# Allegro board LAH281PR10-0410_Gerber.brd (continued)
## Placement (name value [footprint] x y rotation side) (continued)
PC515  4.7U_0402_6.3V6M  [C_0402]  353.23 39.02 270 top
PC520  22U_0603_6.3V6M  [C_0603]  338.03 3.33 270 top
PC521  22U_0603_6.3V6M  [C_0603]  335.24 9.6 90 top
PC522  22U_0603_6.3V6M  [C_0603]  336.64 9.6 90 top
PC523  22U_0603_6.3V6M  [C_0603]  338.04 9.6 90 top
PC524  0.1U_0402_25V6  [C_0402]  314.91 7.58 270 top
PC525  22U_0603_6.3V6M  [C_0603]  336.63 3.36 270 top
PC526  1000P_0402_50V7K  [C_0402]  322.63 3.2 270 top
PC527  680P_0402_50V7K  [C_0402]  331.1 11.19 0 top
PC528  2200P_0402_50V7K  [C_0402]  315.8 7.58 270 top
PC529  22U_0603_6.3V6M  [C_0603]  335.23 3.33 270 top
PC530  10U_0805_25V6K  [C_0805]  317.32 8.1 270 top
PC531  0.1U_0603_25V7K  [C_0603]  324.56 10.75 270 top
PC532  10U_0805_25V6K  [C_0805]  319.1 7.98 270 top
PC533  4.7U_0402_6.3V6M  [C_0402]  324.86 3.31 270 top
PC700  0.1U_0402_25V6  [C_0402]  74.26 29.66 270 top
PC701  0.1U_0402_25V6  [C_0402]  74.21 27.12 0 top
PC702  0.01U_0402_25V6  [C_0402]  75.17 28.75 90 top
PC703  0.1U_0402_25V6  [C_0402]  102.32 6 180 top
PC704  10U_0805_25V6K  [C_0805]  102.32 9.92 180 top
PC705  10U_0805_25V6K  [C_0805]  102.33 8.21 180 top
PC706  2.2U_0402_10V6K  [C_0402]  73.94 21.63 270 top
PC707  1U_0603_25V6K  [C_0603]  74.3 25.47 0 top
PC708  0.047U_0603_25V7M~D  [C_0603]  74.31 24.27 0 top
PC709  2200P_0402_25V7K  [C_0402]  70.19 27.93 90 top
PC710  2200P_0402_50V7K  [C_0402]  102.34 6.9 180 top
PC711  100P_0402_50V8J  [C_0402]  67.73 28.83 270 top
PC712  100P_0402_50V8J  [C_0402]  65.55 26.2 0 top
PC713  10U_0805_25V6K  [C_0805]  71.88 8.01 90 bottom
PC714  10U_0805_25V6K  [C_0805]  73.61 8.01 90 bottom
PC715  10U_0805_25V6K  [C_0805]  71.87 8.01 90 top
PC716  10U_0805_25V6K  [C_0805]  73.61 8.01 90 top
PC717  680P_0402_50V7K  [C_0402]  96.92 2.76 0 top
PC718  0.1U_0402_25V6  [C_0402]  72.7 19.56 270 top
PC719  0.1U_0402_25V6  [C_0402]  71.95 17.79 180 top
PC720  0.1U_0402_25V6  [C_0402]  70.24 18.65 90 top
PC725  0.01U_0402_25V7K  [C_0402]  69.75 16.04 180 top
PC800  0.1U_0402_25V6  [C_0402]  103.9 34.06 270 top
PC801  2200P_0402_50V7K  [C_0402]  103.01 34.06 270 top
PC802  4.7U_0805_25V6K~D  [C_0805]  104.7 37.61 0 top
PC803  4.7U_0805_25V6K~D  [C_0805]  104.7 35.89 0 top
PC804  .1U_0603_25V7K  [C_0603]  106.44 33.13 90 top
PC805  4.7U_0402_6.3V6M  [C_0402]  107.58 33.53 90 top
PC806  330U_D2_2VM_R9M  [C_D2]  113.66 49.56 270 top
PC807  0.047U_0402_25V7K  [C_0402]  106.35 26.89 270 top
PC808  680P_0402_50V7K  [C_0402]  111.45 39.72 90 top
PC900  10U_0603_6.3V6M  [C_0603]  98.71 16.25 0 top
PC901  10U_0603_6.3V6M  [C_0603]  98.71 17.44 0 top
PC902  0.1U_0402_16V7K  [C_0402]  100.44 21.73 90 top
PC903  680P_0402_50V7K  [C_0402]  105.71 22.37 0 top
PC904  68P_0402_50V8J  [C_0402]  99.47 22.65 270 top
PC905  22U_0603_6.3V6M  [C_0603]  108.49 18.01 270 top
PC906  22U_0603_6.3V6M  [C_0603]  107.27 18.01 270 top
PC1100  1000P_0402_50V7K  [C_0402]  309.32 45.6 180 top
PC1101  10U_0402_6.3V6M  [C_0402]  312.29 38.12 270 top
PC1102  0.01UF_0402_25V7K  [C_0402]  308.42 43.83 270 top
PC1103  1000P_0402_50V7K  [C_0402]  309.9 50.89 90 top
PC1104  2200P_0402_50V7K  [C_0402]  309.32 43.83 270 top
PC1105  1000P_0402_50V7K  [C_0402]  308.61 49.48 270 top
PC1106  470P_0402_50V8J  [C_0402]  305.96 42.44 0 bottom
PC1107  0.015U_0402_25V7K  [C_0402]  308.92 47.39 270 top
PC1108  100P_0402_50V8J  [C_0402]  310.71 46.48 180 top
PC1109  1000P_0402_50V7K  [C_0402]  305.93 49.57 0 bottom
PC1110  2200P_0402_50V7K  [C_0402]  305.68 50.51 0 bottom
PC1111  1000P_0402_50V7K  [C_0402]  306.9 34.99 180 top
PC1112  2200P_0402_50V7K  [C_0402]  306.07 36.78 270 top
PC1113  15P_0402_50V8J  [C_0402]  305.08 47.72 90 top
PC1114  470P_0402_50V8J  [C_0402]  306.78 49.57 270 top
PC1115  2200P_0402_50V7K  [C_0402]  304.15 49.53 0 top
PC1116  470P_0402_50V8J  [C_0402]  305.13 34.29 180 top
PC1117  15P_0402_50V8J  [C_0402]  304.29 35.93 180 top
PC1118  470P_0402_50V8J  [C_0402]  304.12 45.37 90 bottom
PC1119  2200P_0402_50V7K  [C_0402]  303.34 34.16 90 top
PC1120  470P_0402_50V8J  [C_0402]  303.93 39.51 180 bottom
PC1121  56P_0402_50V8J  [C_0402]  302.4 47.75 180 top
PC1122  1000P_0402_50V7K  [C_0402]  301.49 48.66 0 top
PC1123  0.22U_0402_25V6K  [C_0402]  302.38 45.39 90 bottom
PC1124  100P_0402_50V8J  [C_0402]  300.55 34.17 180 top
PC1125  1000P_0402_50V7K  [C_0402]  300.55 35.05 180 top
PC1126  0.22U_0402_25V6K  [C_0402]  301.24 39.51 0 bottom
PC1127  0.1U_0402_25V6  [C_0402]  297.08 46.5 180 bottom
PC1128  0.01U_0402_50V7K  [C_0402]  296.16 47.51 0 top
PC1129  0.1U_0402_25V6  [C_0402]  297.84 40.4 180 top
PC1130  4.7U_0402_6.3V6M  [C_0402]  297.32 44.08 180 top
PC1131  0.1U_0402_25V6  [C_0402]  300.15 48.62 270 top
PC1132  0.1U_0402_25V6  [C_0402]  299.94 37.32 180 top
PC1133  0.1U_0402_25V6  [C_0402]  299.26 48.59 270 top
PC1135  0.1U_0402_25V6  [C_0402]  298.37 48.61 270 top
PC1136  0.1U_0402_25V6  [C_0402]  297.05 39 0 top
PC1137  3300P_0402_50V7K~D  [C_0402]  306.9 44.15 180 bottom
PC1140  2200P_0402_50V7K  [C_0402]  311.27 49.48 270 top
PC1204  100U_D3L_25VM_R60M  [C_T521D107M025ATE060]  296.26 17.34 0 top
PC1205  100U_D3L_25VM_R60M  [C_T521D107M025ATE060]  294.86 29.86 0 top
PC1206  2200P_0402_50V7K  [C_0402]  290.78 61.84 90 top
PC1207  0.1U_0402_25V7K  [C_0402]  290.78 61.84 90 bottom
PC1208  10U_0805_25VAK  [C_0805]  287.71 60.9 90 bottom
PC1209  10U_0805_25VAK  [C_0805]  289.46 60.9 90 bottom
PC1210  10U_0805_25VAK  [C_0805]  289.46 60.9 90 top
PC1211  10U_0805_25VAK  [C_0805]  287.71 60.9 90 top
PC1213  1U_0603_16V7K  [C_0603]  293.15 55.8 90 top
PC1214  0.22U_0603_25V7K  [C_0603]  293.19 59.58 180 top
PC1215  2.2U_0603_10V7K  [C_0603]  291.81 54.7 0 top
PC1216  1000P_0603_50V7K  [C_0603]  284.24 54.62 180 bottom
PC1217  2200P_0402_50V7K  [C_0402]  291.35 50.8 90 top
PC1218  0.1U_0402_25V7K  [C_0402]  291.35 50.8 90 bottom
PC1219  10U_0805_25VAK  [C_0805]  290.01 49.84 90 top
PC1220  10U_0805_25VAK  [C_0805]  290.01 49.84 90 bottom
PC1221  10U_0805_25VAK  [C_0805]  287.98 49.84 90 bottom
PC1222  10U_0805_25VAK  [C_0805]  287.98 49.84 90 top
PC1223  1U_0603_16V7K  [C_0603]  293.47 44.77 90 top
PC1224  0.22U_0603_25V7K  [C_0603]  293.42 48.55 180 top
PC1225  2.2U_0603_10V7K  [C_0603]  291.99 43.65 0 top
PC1226  1000P_0603_50V7K  [C_0603]  284.11 43.83 0 bottom
PC1227  2200P_0402_50V7K  [C_0402]  291.54 41.31 90 bottom
PC1228  0.1U_0402_25V7K  [C_0402]  291.54 41.31 90 top
PC1229  10U_0805_25VAK  [C_0805]  290.22 40.39 90 bottom
PC1230  10U_0805_25VAK  [C_0805]  288.47 40.41 90 bottom
PC1231  10U_0805_25VAK  [C_0805]  290.22 40.39 90 top
PC1232  10U_0805_25VAK  [C_0805]  288.47 40.41 90 top
PC1233  0.22U_0603_25V7K  [C_0603]  293.29 38.83 180 top
PC1234  1U_0603_16V7K  [C_0603]  293.21 35.05 90 top
PC1235  2.2U_0603_10V7K  [C_0603]  291.89 33.92 0 top
PC1236  1000P_0603_50V7K  [C_0603]  283.86 34.94 0 bottom
PC1237  2200P_0402_50V7K  [C_0402]  288.54 32.49 180 bottom
PC1238  0.1U_0402_25V7K  [C_0402]  288.54 32.49 180 top
PC1239  10U_0805_25VAK  [C_0805]  288.83 29.35 180 top
PC1240  10U_0805_25VAK  [C_0805]  288.83 29.35 180 bottom
PC1241  10U_0805_25VAK  [C_0805]  288.83 31.13 180 bottom
PC1242  10U_0805_25VAK  [C_0805]  288.83 31.13 180 top
PC1243  0.22U_0603_25V7K  [C_0603]  293.17 27.58 180 top
PC1244  1U_0603_16V7K  [C_0603]  293.13 23.88 90 top
PC1245  2.2U_0603_10V7K  [C_0603]  291.79 22.79 0 top
PC1246  1000P_0603_50V7K  [C_0603]  284.17 23.19 90 bottom
PC1300  330U_D2_2.5V_R6M  [C_D2]  272.67 42.1 0 bottom
PC1301  330U_D2_2.5V_R6M  [C_D2]  272.46 56.89 0 bottom
PC1302  22U_0603_6.3VAM  [C_0603]  269.69 45.3 270 top
PC1303  22U_0603_6.3VAM  [C_0603]  250.59 53.04 90 bottom
PC1304  22U_0603_6.3VAM  [C_0603]  249.4 57.26 270 bottom
PC1305  22U_0603_6.3VAM  [C_0603]  241.4 53.08 90 bottom
PC1306  22U_0603_6.3VAM  [C_0603]  269.73 54.18 270 bottom
PC1307  22U_0603_6.3VAM  [C_0603]  249.34 53.03 90 bottom
PC1308  22U_0603_6.3VAM  [C_0603]  269.69 49.74 270 top
PC1309  22U_0603_6.3VAM  [C_0603]  268.47 49.75 270 bottom
PC1310  22U_0603_6.3VAM  [C_0603]  269.69 49.75 270 bottom
PC1311  22U_0603_6.3VAM  [C_0603]  268.48 58.09 270 top
PC1312  22U_0603_6.3VAM  [C_0603]  268.48 49.76 270 top
PC1313  22U_0603_6.3VAM  [C_0603]  268.5 54.18 270 bottom
PC1314  22U_0603_6.3VAM  [C_0603]  269.75 58.09 270 top
PC1315  22U_0603_6.3VAM  [C_0603]  269.69 45.3 270 bottom
PC1316  22U_0603_6.3VAM  [C_0603]  269.72 54.18 270 top
PC1317  22U_0603_6.3VAM  [C_0603]  242.7 53.05 90 bottom
PC1318  22U_0603_6.3VAM  [C_0603]  243.95 53.05 90 bottom
PC1319  22U_0603_6.3VAM  [C_0603]  250.61 57.28 270 bottom
PC1320  22U_0603_6.3VAM  [C_0603]  269.74 58.09 270 bottom
PC1321  22U_0603_6.3VAM  [C_0603]  268.47 58.08 270 bottom
PC1322  22U_0603_6.3VAM  [C_0603]  248.06 53.05 90 bottom
PC1323  22U_0603_6.3VAM  [C_0603]  268.5 54.18 270 top
PC1324  10U_0402_6.3VAM  [C_0402]  248.8 52.02 270 bottom
PC1325  10U_0402_6.3VAM  [C_0402]  245.87 48.93 90 bottom
PC1326  10U_0402_6.3VAM  [C_0402]  242.2 48.98 90 bottom
PC1327  10U_0402_6.3VAM  [C_0402]  246.96 53.57 90 bottom
PC1328  10U_0402_6.3VAM  [C_0402]  246.96 52.02 270 bottom
PC1329  10U_0402_6.3VAM  [C_0402]  247.91 52.02 270 bottom
PC1330  10U_0402_6.3VAM  [C_0402]  245.99 52.02 270 bottom
PC1331  10U_0402_6.3VAM  [C_0402]  241.25 48.98 90 bottom
PC1332  10U_0402_6.3VAM  [C_0402]  249.69 52.02 270 bottom
PC1333  10U_0402_6.3VAM  [C_0402]  244.93 48.93 90 bottom
PC1334  10U_0402_6.3VAM  [C_0402]  244.13 52.02 270 bottom
PC1335  10U_0402_6.3VAM  [C_0402]  243.11 48.97 90 bottom
PC1336  10U_0402_6.3VAM  [C_0402]  245.04 53.6 90 bottom
PC1337  10U_0402_6.3VAM  [C_0402]  245.05 52.02 270 bottom
PC1338  10U_0402_6.3VAM  [C_0402]  244.01 48.95 90 bottom
PC1339  10U_0402_6.3VAM  [C_0402]  242.3 52.01 270 bottom
PC1340  10U_0402_6.3VAM  [C_0402]  245.99 53.58 90 bottom
PC1341  10U_0402_6.3VAM  [C_0402]  250.65 52.02 270 bottom
PC1342  10U_0402_6.3VAM  [C_0402]  246.81 48.91 90 bottom
PC1343  10U_0402_6.3VAM  [C_0402]  243.22 52.02 270 bottom
PC1344  10U_0402_6.3VAM  [C_0402]  241.35 52.04 270 bottom
PC1345  1U_0201_6.3VAM  [C_0201]  245.14 47.75 270 bottom
PC1346  1U_0201_6.3VAM  [C_0201]  245.72 47.73 270 bottom
PC1347  1U_0201_6.3VAM  [C_0201]  246.31 47.73 270 bottom
PC1348  1U_0201_6.3VAM  [C_0201]  242.21 47.77 270 bottom
PC1349  1U_0201_6.3VAM  [C_0201]  241.62 47.76 270 bottom
PC1350  1U_0201_6.3VAM  [C_0201]  241.66 45.47 90 bottom
PC1351  1U_0201_6.3VAM  [C_0201]  241.05 45.48 90 bottom
PC1352  1U_0201_6.3VAM  [C_0201]  242.24 45.48 90 bottom
PC1353  1U_0201_6.3VAM  [C_0201]  248.77 48.15 270 bottom
PC1354  1U_0201_6.3VAM  [C_0201]  248.2 48.16 270 bottom
PC1355  1U_0201_6.3VAM  [C_0201]  247.61 48.15 270 bottom
PC1356  1U_0201_6.3VAM  [C_0201]  244.04 45.49 90 bottom
PC1357  1U_0201_6.3VAM  [C_0201]  243.43 45.5 90 bottom
PC1358  1U_0201_6.3VAM  [C_0201]  242.83 45.49 90 bottom
PC1359  1U_0201_6.3VAM  [C_0201]  245.85 45.48 90 bottom
PC1360  1U_0201_6.3VAM  [C_0201]  245.26 45.47 90 bottom
PC1361  1U_0201_6.3VAM  [C_0201]  244.65 45.48 90 bottom
PC1362  1U_0201_6.3VAM  [C_0201]  251.89 49.74 270 bottom
PC1363  1U_0201_6.3VAM  [C_0201]  252.46 49.74 270 bottom
PC1364  1U_0201_6.3VAM  [C_0201]  251.98 50.68 90 bottom
PC1365  1U_0201_6.3VAM  [C_0201]  244.54 47.75 270 bottom
PC1366  1U_0201_6.3VAM  [C_0201]  243.94 47.75 270 bottom
PC1367  1U_0201_6.3VAM  [C_0201]  249.35 48.16 270 bottom
PC1368  1U_0201_6.3VAM  [C_0201]  251.99 56.82 270 bottom
PC1369  1U_0201_6.3VAM  [C_0201]  243.36 47.75 270 bottom
PC1370  1U_0201_6.3VAM  [C_0201]  242.78 47.75 270 bottom
PC1371  1U_0201_6.3VAM  [C_0201]  252.57 54.91 270 bottom
PC1372  1U_0201_6.3VAM  [C_0201]  250.54 48.16 270 bottom
PC1373  1U_0201_6.3VAM  [C_0201]  249.9 49.37 90 bottom
PC1374  1U_0201_6.3VAM  [C_0201]  248.14 49.35 90 bottom
PC1375  1U_0201_6.3VAM  [C_0201]  247.55 49.36 90 bottom
PC1376  1U_0201_6.3VAM  [C_0201]  241.05 47.76 270 bottom
PC1377  1U_0201_6.3VAM  [C_0201]  252.55 50.68 90 bottom
PC1378  1U_0201_6.3VAM  [C_0201]  250.15 45.8 90 bottom
PC1379  1U_0201_6.3VAM  [C_0201]  250.73 45.81 90 bottom
PC1380  1U_0201_6.3VAM  [C_0201]  248.72 49.35 90 bottom
PC1381  1U_0201_6.3VAM  [C_0201]  250.49 49.34 90 bottom
PC1382  1U_0201_6.3VAM  [C_0201]  249.31 49.36 90 bottom
PC1383  1U_0201_6.3VAM  [C_0201]  246.9 47.76 270 bottom
PC1384  1U_0201_6.3VAM  [C_0201]  249.94 48.15 270 bottom
PC1385  1U_0201_6.3VAM  [C_0201]  248.3 45.81 90 bottom
PC1386  1U_0201_6.3VAM  [C_0201]  248.93 45.81 90 bottom
PC1387  1U_0201_6.3VAM  [C_0201]  249.57 45.81 90 bottom
PC1388  1U_0201_6.3VAM  [C_0201]  246.45 45.48 90 bottom
PC1389  1U_0201_6.3VAM  [C_0201]  247.04 45.48 90 bottom
PC1390  1U_0201_6.3VAM  [C_0201]  247.69 45.8 90 bottom
PC1391  1U_0201_6.3VAM  [C_0201]  252.55 56.82 270 bottom
PC1392  1U_0201_6.3VAM  [C_0201]  252.01 54.91 270 bottom
PC1393  330U_D2_2.5V_R6M  [C_D2]  272.76 47.25 0 bottom
PC1394  330U_D2_2.5V_R6M  [C_D2]  242.85 42.57 0 bottom
PC1395  22U_0603_6.3VAM  [C_0603]  267.23 58.1 270 bottom
PC1396  22U_0603_6.3VAM  [C_0603]  267.23 58.1 270 top
PC1397  22U_0603_6.3VAM  [C_0603]  268.46 45.3 270 bottom
PC1398  22U_0603_6.3VAM  [C_0603]  268.46 45.3 270 top
PC1399  22U_0603_6.3VAM  [C_0603]  267.26 54.18 270 top
PC1400  22U_0603_6.3VAM  [C_0603]  267.26 54.18 270 bottom
PC1401  10U_0402_6.3VAM  [C_0402]  241.95 57.74 90 bottom
PC1402  10U_0402_6.3VAM  [C_0402]  240.14 56.66 270 bottom
PC1403  10U_0402_6.3VAM  [C_0402]  241.06 56.72 270 bottom
PC1404  10U_0402_6.3VAM  [C_0402]  242.91 56.71 270 bottom
PC1405  10U_0402_6.3VAM  [C_0402]  241.98 56.68 270 bottom
PC1406  10U_0402_6.3VAM  [C_0402]  243.81 56.7 270 bottom
PC1407  10U_0402_6.3VAM  [C_0402]  245.67 56.7 270 bottom
PC1408  10U_0402_6.3VAM  [C_0402]  246.58 56.7 270 bottom
PC1409  10U_0402_6.3VAM  [C_0402]  248.36 56.68 270 bottom
PC1410  10U_0402_6.3VAM  [C_0402]  245.67 57.75 90 bottom
PC1411  10U_0402_6.3VAM  [C_0402]  246.58 57.75 90 bottom
PC1412  10U_0402_6.3VAM  [C_0402]  248.36 57.74 90 bottom
PC1413  10U_0402_6.3VAM  [C_0402]  247.47 57.75 90 bottom
PC1414  10U_0402_6.3VAM  [C_0402]  240.99 57.72 90 bottom
PC1415  10U_0402_6.3VAM  [C_0402]  242.86 57.75 90 bottom
PC1416  10U_0402_6.3VAM  [C_0402]  250.51 58.24 0 bottom
PC1417  10U_0402_6.3VAM  [C_0402]  252.17 52.64 90 bottom
PC1418  10U_0402_6.3VAM  [C_0402]  247.47 56.68 270 bottom
PC1419  10U_0402_6.3VAM  [C_0402]  244.74 56.68 270 bottom
PC1420  10U_0402_6.3VAM  [C_0402]  244.74 57.75 90 bottom
PC1421  10U_0402_6.3VAM  [C_0402]  243.81 57.75 90 bottom
PC1500  470U_X_2VM_R6M  [C_X]  275.84 14.62 180 bottom
PC1502  22U_0603_6.3VAM  [C_0603]  267 29.4 45 top
PC1503  22U_0603_6.3VAM  [C_0603]  267.01 29.39 45 bottom
PC1504  22U_0603_6.3VAM  [C_0603]  266.13 30.26 45 bottom
PC1505  22U_0603_6.3VAM  [C_0603]  246.52 39.51 0 bottom
PC1506  22U_0603_6.3VAM  [C_0603]  267.85 28.53 45 top
PC1507  22U_0603_6.3VAM  [C_0603]  269.62 26.68 45 bottom
PC1508  22U_0603_6.3VAM  [C_0603]  268.69 27.63 45 top
PC1509  22U_0603_6.3VAM  [C_0603]  268.7 27.63 45 bottom
PC1510  22U_0603_6.3VAM  [C_0603]  269.61 26.67 45 top
PC1511  22U_0603_6.3VAM  [C_0603]  267.85 28.52 45 bottom
PC1512  22U_0603_6.3VAM  [C_0603]  250.33 39.51 180 bottom
PC1513  22U_0603_6.3VAM  [C_0603]  241.31 39.51 0 bottom
PC1514  22U_0603_6.3VAM  [C_0603]  245.48 39.61 180 bottom
PC1515  10U_0402_6.3VAM  [C_0402]  249.19 36.74 90 bottom
PC1516  10U_0402_6.3VAM  [C_0402]  247.39 36.75 90 bottom
PC1517  10U_0402_6.3VAM  [C_0402]  244.69 36.79 90 bottom
PC1518  10U_0402_6.3VAM  [C_0402]  248.3 36.74 90 bottom
PC1519  10U_0402_6.3VAM  [C_0402]  241.9 36.78 90 bottom
PC1520  10U_0402_6.3VAM  [C_0402]  245.62 36.75 90 bottom
PC1521  10U_0402_6.3VAM  [C_0402]  242.82 36.79 90 bottom
PC1522  10U_0402_6.3VAM  [C_0402]  246.5 36.75 90 bottom
PC1523  10U_0402_6.3VAM  [C_0402]  240.97 36.77 90 bottom
PC1524  10U_0402_6.3VAM  [C_0402]  243.77 36.81 90 bottom
PC1525  1U_0201_6.3VAM  [C_0201]  250.58 38.53 270 bottom
PC1526  1U_0201_6.3VAM  [C_0201]  251.16 38.54 270 bottom
PC1527  1U_0201_6.3VAM  [C_0201]  249.97 36.62 90 bottom
PC1528  1U_0201_6.3VAM  [C_0201]  250.56 36.62 90 bottom
PC1529  1U_0201_6.3VAM  [C_0201]  251.15 36.63 90 bottom
PC1530  1U_0201_6.3VAM  [C_0201]  252.14 40.36 90 bottom
PC1531  1U_0201_6.3VAM  [C_0201]  252.73 40.35 90 bottom
PC1532  1U_0201_6.3VAM  [C_0201]  252.84 37.39 90 bottom
PC1533  1U_0201_6.3VAM  [C_0201]  252.81 39.2 270 bottom
PC1534  1U_0201_6.3VAM  [C_0201]  252.26 37.39 90 bottom
PC1535  1U_0201_6.3VAM  [C_0201]  250 38.54 270 bottom
PC1536  1U_0201_6.3VAM  [C_0201]  252.23 39.2 270 bottom
PC1600  22U_0603_6.3VAM  [C_0603]  273.61 61.11 270 top
PC1601  22U_0603_6.3VAM  [C_0603]  272.39 61.11 270 top
PC1602  22U_0603_6.3VAM  [C_0603]  271.14 61.11 270 top
PC1603  22U_0603_6.3VAM  [C_0603]  269.9 61.11 270 top
PC1604  22U_0603_6.3VAM  [C_0603]  268.71 61.11 270 top
PC1605  22U_0603_6.3VAM  [C_0603]  268.71 61.11 270 bottom
PC1606  22U_0603_6.3VAM  [C_0603]  269.9 61.11 270 bottom
PC1607  22U_0603_6.3VAM  [C_0603]  271.14 61.11 270 bottom
PC1608  22U_0603_6.3VAM  [C_0603]  272.39 61.11 270 bottom
PC1609  22U_0603_6.3VAM  [C_0603]  273.61 61.11 270 bottom
PC1610  10U_0402_6.3VAM  [C_0402]  274.71 61.11 270 bottom
PC1611  10U_0402_6.3VAM  [C_0402]  267.58 60.8 270 top
PC1612  10U_0402_6.3VAM  [C_0402]  266.67 60.8 270 top
PC1613  10U_0402_6.3VAM  [C_0402]  265.76 60.8 270 top
PC1614  10U_0402_6.3VAM  [C_0402]  267.58 60.8 270 bottom
PC1615  10U_0402_6.3VAM  [C_0402]  266.67 60.8 270 bottom
PC1616  10U_0402_6.3VAM  [C_0402]  265.76 60.8 270 bottom
PC1617  1U_0201_6.3VAM  [C_0201]  274.58 60.95 270 top
PC1700  2200P_0402_50V7K  [C_0402]  293.32 19.76 90 top
PC1701  0.1U_0402_25V7K  [C_0402]  293.32 19.76 90 bottom
PC1702  10U_0603_25V6M  [C_0603]  291.02 19.7 90 bottom
PC1703  10U_0603_25V6M  [C_0603]  292.25 19.66 90 bottom
PC1704  10U_0603_25V6M  [C_0603]  291.02 19.7 90 top
PC1705  10U_0603_25V6M  [C_0603]  292.25 19.66 90 top
PC1706  0.22U_0603_25V7K  [C_0603]  293.38 17.67 180 top
PC1707  1U_0603_16V7K  [C_0603]  293.29 13.92 90 top
PC1708  2.2U_0603_10V7K  [C_0603]  291.98 12.71 0 top
PC1709  1000P_0603_50V7K  [C_0603]  285 13.27 90 bottom
PC1710  10U_0603_25V6M  [C_0603]  289.82 19.69 90 bottom
PC1711  10U_0603_25V6M  [C_0603]  288.61 19.68 90 bottom
PC1712  10U_0603_25V6M  [C_0603]  289.82 19.69 90 top
PC1713  10U_0603_25V6M  [C_0603]  288.61 19.68 90 top
PC1800  2200P_0402_50V7K  [C_0402]  289.41 71.59 90 bottom
PC1801  0.1U_0402_25V7K  [C_0402]  289.41 71.59 90 top
PC1802  10U_0805_25VAK  [C_0805]  288.05 70.81 90 top
PC1803  10U_0805_25VAK  [C_0805]  288.05 70.81 90 bottom
PC1804  10U_0805_25VAK  [C_0805]  286.35 70.84 90 top
PC1805  10U_0805_25VAK  [C_0805]  286.35 70.84 90 bottom
PC1806  0.22U_0603_25V7K  [C_0603]  291.18 69.44 180 top
PC1807  1U_0603_16V7K  [C_0603]  291.07 65.68 90 top
PC1808  2.2U_0603_10V7K  [C_0603]  289.76 64.58 0 top
PC1809  1000P_0603_50V7K  [C_0603]  282.33 63.77 180 bottom
PC2003  1500P_0402_50V7K  [C_0402]  53.22 21.7 270 top
PC2007  0.01U_0402_25V7K~D  [C_0402]  50.24 17.49 270 bottom
PC2008  0.01U_0402_25V7K~D  [C_0402]  49.35 17.49 270 bottom
PC2009  100P_0402_50V8J~D  [C_0402]  52.54 23.37 90 bottom
PC2010  220P_0402_50V8J~D  [C_0402]  55.05 23.31 90 bottom
PC2011  1200P_0402_50V7K  [C_0402]  50.28 21.36 90 bottom
PC2012  100P_0402_50V8J~D  [C_0402]  52.87 15.4 270 bottom
PC2013  220P_0402_50V8J~D  [C_0402]  55.35 15.4 270 bottom
PC2014  1200P_0402_50V7K  [C_0402]  49.56 15.07 270 bottom
PC2015  0.01U_0402_25V7K~D  [C_0402]  75.45 29.37 180 bottom
PC2016  100P_0402_50V8J~D  [C_0402]  75 24.3 180 bottom
PC2017  220P_0402_50V8J~D  [C_0402]  76.27 24.09 270 bottom
PC2018  1200P_0402_50V7K  [C_0402]  73.66 28.21 90 bottom
PC2019  10U 10V M X5R 0402  [C_0402]  37.61 18.63 0 bottom
PC2020  100P_0402_50V8J  [C_0402]  34.88 15.65 270 bottom
PC2021  2.2U 25V M X5R 0402  [C_0402]  37.63 13.88 270 bottom
PC2022  0.1U 25V M X5R 0402  [C_0402]  38.54 13.88 270 bottom
PC2023  10U 10V M X5R 0402  [C_0402]  41.88 18.61 0 bottom
PC2024  100P_0402_50V8J  [C_0402]  45.75 16.44 270 bottom
PC2025  2.2U 25V M X5R 0402  [C_0402]  45.69 14.59 0 bottom
PC2026  0.1U 25V M X5R 0402  [C_0402]  45.74 13.65 0 bottom
PC2100  0.022U_0402_25V7K  [C_0402]  37.11 33.77 90 top
PC2102  0.022U_0402_25V7K  [C_0402]  41.45 33.45 180 top
PC2103  0.1U_0402_25V6  [C_0402]  87.28 32.36 270 bottom
PC2104  220P_0402_50V8J  [C_0402]  82.83 24.53 180 bottom
PC2105  100P_0402_50V8J  [C_0402]  83.18 27.95 0 bottom
PC2106  1200P_0402_50V7K  [C_0402]  82.32 28.82 180 bottom
PD1  SX34-SMA2  [SBR3A40SA-13_SMA2]  97.28 43.35 90 bottom
PD2  VZ0603M260APT_0603  [D_0603]  95.08 62.33 180 bottom
PD3  AZ5125-02S.R7G_SOT23-3  [L03ESDL5V0CC3-2_SOT23-3]  86.46 26.52 180 bottom
PD4  -  [SS5P10-M3-86A_TO277A3]  84.03 38.35 90 bottom
PD6  -  [SS5P10-M3-86A_TO277A3]  84.06 38.36 270 top
PD8  -  [BAS40CW_SOT323-3]  302.48 28.82 180 bottom
PD9  AZ5A25-02R_SOT523-3  [TVNST52302AB0_SOT523-3]  64.97 16.59 180 top
PD10  AZ5A25-02R_SOT523-3  [TVNST52302AB0_SOT523-3]  67 18.11 0 top
PD11  BAT54CW-7-F SOT-323  [BAT54CW_SOT323-3]  85.58 27.53 90 top
PD12  BAT54CW-7-F SOT-323  [BAT54CW_SOT323-3]  53.8 24.5 270 top
PD13  BAT54CW-7-F SOT-323  [BAT54CW_SOT323-3]  51.61 33.82 90 bottom
PD14  BAT54CW-7-F SOT-323  [BAT54CW_SOT323-3]  51.89 34.05 270 top
PD15  BAT54CW-7-F SOT-323  [BAT54CW_SOT323-3]  48.08 32.78 180 top
PD200  30MA_30V_0.5UA_0.4V_SOD323-2  [D_SOD323-2]  112.64 6.92 0 top
PD700  BAT54CW-7-F SOT-323  [BAT54CW_SOT323-3]  80.32 27.42 90 top
PD701  BAT54CW-7-F SOT-323  [BAT54CW_SOT323-3]  79 27.43 270 top
PD702  -  [MM3Z22VST1G_SOD323-2]  75.26 20.89 0 top
PD2004  RB751V-40_SOD323-2  [SDMK0340L-7-F_SOD323-2]  36.24 17.24 270 bottom
PD2005  RB751V-40_SOD323-2  [SDMK0340L-7-F_SOD323-2]  44.39 17.25 270 bottom
PH1100  100K_0402_1%_TSM0B104F4251RZ  [R_0402]  277.54 63.38 180 top
PH1101  220K_0402_5%_ERTJ0EV224J  [R_0402]  280.77 53.12 180 top
PH1102  220K_0402_5%_ERTJ0EV224J  [R_0402]  279.32 12.93 0 top
PH1103  220K_0402_5%_ERTJ0EV224J  [R_0402]  290.73 53.04 180 top
PH1104  220K_0402_5%_ERTJ0EV224J  [R_0402]  290.52 12.14 180 top
PJP1  PAD-OPEN1x1m  [JUMP_43X39]  270.89 73.93 0 bottom
PJP2  PAD-OPEN1x1m  [JUMP_43X39]  268.09 82.18 0 top
PJP3  -  [JUMP_43X79]  148.13 36.68 0 bottom
PJP5  -  [JUMP_43X79]  25.83 60.71 90 bottom
PJP6  PAD-OPEN1x1m  [JUMP_43X39]  47.61 56.7 270 top
PJP12  PAD-OPEN1x1m  [JUMP_43X39]  109.26 147.55 270 bottom
PJP17  PAD-OPEN1x2m  [JUMP_43X79]  376.02 33.28 270 top
PJP18  PAD-OPEN1x1m  [JUMP_43X39]  389.4 13.49 0 bottom
PJP19  PAD-OPEN1x1m  [JUMP_43X39]  386.3 15.39 270 top
PJP20  PAD-OPEN1x1m  [JUMP_43X39]  126.03 68.71 0 top
PJP22  PAD-OPEN1x1m  [JUMP_43X39]  128.81 67.97 0 top
PJP27  PAD-OPEN1x1m  [JUMP_43X39]  376.35 58.7 180 bottom
PJP28  PAD-OPEN1x1m  [JUMP_43X39]  379.57 46.94 90 bottom
PJP30  -  [JUMP_43X79]  328.84 16.4 0 top
PJP32  PAD-OPEN1x1m  [JUMP_43X39]  368.25 13.05 270 top
PJP35  PAD-OPEN1x1m  [JUMP_43X39]  36.98 3.08 90 top
PJP36  -  [JUMP_43X79]  145.15 107.98 270 top
PJP37  -  [JUMP_43X79]  150.99 107.85 270 top
PJP38  -  [JUMP_43X79]  143.35 16.65 180 top
PJP39  -  [JUMP_43X79]  372.1 31.51 180 top
PJP40  PAD-OPEN 4x4m  [JUMP_43X118]  373.67 36.98 180 top
PJP42  -  [JUMP_43X79]  339.64 13.37 180 top
PJP43  -  [JUMP_43X79]  294.16 70.5 0 top
PJP62  -  [JUMP_43X79]  357.81 9.57 90 bottom
PJP63  -  [JUMP_43X79]  131.05 84.98 180 bottom
PJP64  -  [JUMP_43X79]  332.05 25.2 270 top
PJP65  -  [JUMP_43X79]  294.16 64.78 0 top
PJP66  -  [JUMP_43X79]  89.06 57.42 0 top
PJP67  -  [JUMP_43X118]  130.78 94.92 90 top
PJP69  PAD-OPEN1x2m  [JUMP_43X79]  25.54 7.01 180 bottom
PJP100  PAD-OPEN 1x2m~D  [JUMP_43X79]  143.17 114.83 180 top
PJP101  -  [JUMP_43X118]  143.49 102.21 0 bottom
PJP102  PAD-OPEN 1x2m~D  [JUMP_43X79]  55.07 12.44 270 bottom
PJP103  -  [JUMP_43X118]  41.52 7.56 180 top
PJP200  PAD-OPEN 1x2m  [JUMP_43X79]  117.31 4.45 90 top
PJP202  JUMP_1x3m  [JUMP_43X118]  145.96 10.1 180 top
PJP203  JUMP_1x3m  [JUMP_43X118]  145.96 4.85 180 top
PJP204  PAD-OPEN1x1m  [JUMP_43X39]  117.57 14.42 180 top
PJP300  -  [JUMP_43X79]  311.73 53.82 90 top
PJP301  -  [JUMP_43X118]  298.13 57.44 180 top
PJP391  PAD-OPEN1x1m  [JUMP_43X39]  148.59 24.34 0 bottom
PJP400  -  [JUMP_43X79]  153 91.49 0 top
PJP401  -  [JUMP_43X79]  165.81 92.3 0 top
PJP500  PAD-OPEN 1x2m~D  [JUMP_43X79]  346.87 45.44 0 top
PJP501  -  [JUMP_43X118]  372.53 42.21 0 top
PJP502  -  [JUMP_43X118]  336.46 6.49 0 top
PJP503  PAD-OPEN 1x2m~D  [JUMP_43X79]  318.89 11.01 270 top
PJP700  PAD-OPEN 43x118  [JUMP_43X118-NPM]  106.12 5.94 270 top
PJP701  PAD-OPEN1x1m  [JUMP_43X39]  66.52 27.78 180 top
PJP800  PAD-OPEN 1x2m  [JUMP_43X79]  100.68 36.53 0 top
PJP801  PAD-OPEN 43x118  [JUMP_43X118]  114.05 54.19 0 top
PJP900  PAD-OPEN1x1m  [JUMP_43X39]  96.4 18.28 0 top
PJP901  PAD-OPEN1x1m  [JUMP_43X39]  107.95 20.21 0 top
PJPDC1  ACES_50493-0110N-001  [ACES_50493-0110N-001_11P]  91.24 43.76 90 bottom
PL1  9A Z80 10M 1812_2P  [9A_Z80_1812_2P]  96.95 55.63 0 bottom
PL2  9A Z80 10M 1812_2P  [9A_Z80_1812_2P]  96.95 59.46 0 bottom
PL4  BLM15BX102SN1D_2P  [MURAT_BLM15HG601SN1D_2P]  89.61 27.61 180 bottom
PL5  -  [5A_Z80_0805_2P]  11.63 45.44 270 bottom
PL6  -  [5A_Z80_0805_2P]  13.54 45.44 270 bottom
PL7  -  [5A_Z80_0805_2P]  21.67 65.66 315 top
PL8  -  [5A_Z80_0805_2P]  22.95 66.94 315 top
PL9  9A Z80 10M 1812_2P  [9A_Z80_1812_2P]  113.87 86.69 0 top
PL11  FBMJ4516HS720NT_2P  [TAIYO_FBMJ4516HS720NT_2P]  67.38 10.56 270 top
PL12  FBMJ4516HS720NT_2P  [TAIYO_FBMJ4516HS720NT_2P]  69.72 10.57 270 top
PL100  1.5UH_9A_20%_7X7X3_M  [L_7X7X3_M_2P]  137.55 110.67 270 bottom
PL101  2.2UH_7.8A_20%_7X7X3_M  [L_7X7X3_M_2P]  50.8 7.6 180 top
PL201  0.68UH_PCMC063T-R68MN_15.5A_20%  [CYNTE_PCMC063T-R68MN_2P]  141.26 4.47 180 top
PL300  1UH_6.6A_20%_5X5X3_M  [L_5X5X3_M_2P]  305.6 57.86 180 top
PL400  1UH_PCMB042T-1R0MS_4.5A_20%  [CYNTE_PCMB042T-1R0MS_2P]  160.02 92.49 0 top
PL500  2.2UH_7.8A_20%_7X7X3_M  [L_7X7X3_M_2P]  359.38 43.07 0 top
PL501  1.5UH_9A_20%_7X7X3_M  [L_7X7X3_M_2P]  327.08 6.36 0 top
PL700  1UH_6.6A_20%_5X5X3_M  [L_5X5X3_M_2P]  106.12 7.43 270 top
PL701  2.2UH_7.8A_20%_7X7X3_M  [L_7X7X3_M_2P]  89.21 6 180 top
PL801  1.5UH_MMD-06CZ-1R5M-V1_9A_20%  [L_7X7X3_M_2P]  102.81 47.06 0 top
PL900  1UH_PCMB042T-1R0MS_4.5A_20%  [CYNTE_PCMB042T-1R0MS_2P]  104.32 20.66 270 top
PL1200  -  [5A_Z80_0805_2P]  295.84 12.32 90 top
PL1201  -  [5A_Z80_0805_2P]  297.64 12.32 90 top
PL1202  0.15UH_PCME064T-R15MS_36A_20%  [L_7X7X4_M]  282.45 57.33 180 top
PL1203  0.15UH_PCME064T-R15MS_36A_20%  [L_7X7X4_M]  282.53 47.19 180 top
PL1204  0.15UH_PCME064T-R15MS_36A_20%  [L_7X7X4_M]  282.49 37.61 180 top
PL1205  0.15UH_PCME064T-R15MS_36A_20%  [L_7X7X4_M]  282.5 26.92 180 top
PL1700  0.15UH_PCME064T-R15MS_36A_20%  [L_7X7X4_M]  282.54 17.17 180 top
PL1800  0.47UH_MMD05CZR47M_12A_20%  [MAG_MMD05CZR47M_4P]  280.73 66.63 180 top
PQ1  L2N7002DW1T1G_SC88-6  [DMN65D8LDW-7_SOT363-6]  88.33 20.52 270 top
PQ2  L2N7002DW1T1G_SC88-6  [DMN65D8LDW-7_SOT363-6]  80.13 18.26 270 top
PQ3  L2N7002DW1T1G_SC88-6  [DMN65D8LDW-7_SOT363-6]  84.01 22.63 0 top
PQ4  L2N7002DW1T1G_SC88-6  [DMN65D8LDW-7_SOT363-6]  53.27 29.43 0 top
PQ5  L2N7002DW1T1G_SC88-6  [DMN65D8LDW-7_SOT363-6]  63.97 29.32 180 top
PQ6  L2N7002DW1T1G_SC88-6  [DMN65D8LDW-7_SOT363-6]  54.92 26.42 90 top
PQ7  L2N7002DW1T1G_SC88-6  [DMN65D8LDW-7_SOT363-6]  51.1 29.37 0 bottom
PQ8  L2N7002DW1T1G_SC88-6  [DMN65D8LDW-7_SOT363-6]  63.72 27.26 180 bottom
PQ9  L2N7002DW1T1G_SC88-6  [DMN65D8LDW-7_SOT363-6]  52.71 31.92 270 bottom
PQ10  SI7149DP-T1-GE3_POWERPAKSO8-5  [Q_P_DFN56-8-5]  100.27 52.63 0 bottom
PQ11  SI7149DP-T1-GE3_POWERPAKSO8-5  [Q_P_DFN56-8-5]  99.84 41.05 90 bottom
PQ12  -  [EMB80P03JS_SOT-23-3]  87.44 23.36 270 top
PQ13  -  [EMB80P03JS_SOT-23-3]  79.79 21.2 270 top
PQ14  FDV301N_G_NL_SOT23-3  [FDV301N_NL_SOT23-3]  99.94 29.98 0 top
PQ16  LMBT3904WT1G_SC70-3  [MMST3904-7-F_SOT323-3]  88.97 26.33 0 bottom
PQ17  AOSP21357_SO8  [Q_P_SO8]  72.8 30.96 90 bottom
PQ18  AOSP21357_SO8  [Q_P_SO8]  85.56 34.78 270 bottom
PQ19  -  [EMB80P03JS_SOT-23-3]  50.4 28.06 0 top
PQ20  -  [EMB80P03JS_SOT-23-3]  59.98 27.19 0 top
PQ22  AOSP21357_SO8  [Q_P_SO8]  72.8 34.8 270 top
PQ23  AOSP21357_SO8  [Q_P_SO8]  85.58 30.99 90 top
PQ24  -  [EMB80P03JS_SOT-23-3]  48.27 30.09 0 bottom
PQ25  -  [EMB80P03JS_SOT-23-3]  57.73 28.18 180 bottom
PQ26  -  [L2N7002WT1G_SC70-3]  303.84 32.3 270 bottom
PQ200  AON6380_DFN5X6-8-5  [Q_N_DFN56-8-5]  120.34 2.29 0 top
PQ201  AON6314_DFN5X6-8  [Q_N_DFN56-8-5]  130.2 7.61 180 top
PQ700  SI7149DP-T1-GE3_POWERPAKSO8-5  [Q_P_DFN56-8-5]  92.34 34.2 180 bottom
PQ701  AONS32306_DFN5X6-8-5  [Q_N_DFN56-8-5]  82.86 15.17 270 top
PQ702  AON6380_DFN5X6-8-5  [Q_N_DFN56-8-5]  93.34 14.44 270 top
PQ703  AON6314_DFN5X6-8  [Q_N_DFN56-8-5]  97.56 4.47 90 top
PQ704  L2N7002DW1T1G_SC88-6  [DMN66D0LDW-7_SOT363-6]  75.15 18.18 270 top
PQ705  -  [EMB80P03JS_SOT-23-3]  89.48 37.65 270 top
PQ800  AON7408L_DFN8-5  [Q_N_DFN33-8-5]  103.87 42.32 180 top
PQ801  AON7752_DFN3X3EP8-5  [Q_N_DFN33-8-5]  105.92 39.42 0 top
PQ2001  L2N7002DW1T1G_SC88-6  [DMN65D8LDW-7_SOT363-6]  58.35 15.96 0 top
PQ2002  L2N7002DW1T1G_SC88-6  [DMN65D8LDW-7_SOT363-6]  61.96 16.12 0 top
PQ2003  L2N7002DW1T1G_SC88-6  [DMN65D8LDW-7_SOT363-6]  61.78 21.12 180 top
PQ2004  L2N7002DW1T1G_SC88-6  [DMN65D8LDW-7_SOT363-6]  56.19 20.65 90 top
PQ2005  L2N7002DW1T1G_SC88-6  [DMN65D8LDW-7_SOT363-6]  55.88 16.92 90 top
PQ2006  L2N7002DW1T1G_SC88-6  [DMN65D8LDW-7_SOT363-6]  51.92 20.41 90 top
PQ2007  L2N7002DW1T1G_SC88-6  [DMN65D8LDW-7_SOT363-6]  70.78 26.76 90 bottom
PQ2008  L2N7002DW1T1G_SC88-6  [DMN65D8LDW-7_SOT363-6]  38.82 19.71 180 bottom
PQ2009  L2N7002DW1T1G_SC88-6  [DMN65D8LDW-7_SOT363-6]  42.79 19.6 180 bottom
PQ2010  L2N7002WT1G_SC70-3  [DMN65D8LW-7_SOT323-3]  61.09 24.2 0 top
PQ2012  L2N7002DW1T1G_SC88-6  [DMN65D8LDW-7_SOT363-6]  52.86 15.8 90 top
PQ2100  EMB12P03V_EDFN8-5  [Q_P_DFN33-8-5]  38.58 31.93 180 top
PQ2101  -  [EMB80P03JS_SOT-23-3]  38.05 31.03 180 bottom
PQ2102  L2N7002DW1T1G_SC88-6  [DMN65D8LDW-7_SOT363-6]  34.81 27.81 90 bottom
PQ2104  EMB12P03V_EDFN8-5  [Q_P_DFN33-8-5]  43.56 32.06 180 top
PQ2105  -  [EMB80P03JS_SOT-23-3]  41.98 33.82 0 bottom
PQ2106  L2N7002DW1T1G_SC88-6  [DMN65D8LDW-7_SOT363-6]  40.91 27.56 90 bottom
PQ2108  FDV301N_G_NL_SOT23-3  [FDV301N_NL_SOT23-3]  93.55 25.64 270 bottom
PQ2109  L2N7002DW1T1G_SC88-6  [DMN65D8LDW-7_SOT363-6]  96.61 30.76 180 top
PQ2110  L2N7002DW1T1G_SC88-6  [DMN65D8LDW-7_SOT363-6]  35.67 13.06 270 bottom
PQ2111  L2N7002DW1T1G_SC88-6  [DMN65D8LDW-7_SOT363-6]  43.79 12.78 270 bottom
PQ2112  L2N7002DW1T1G_SC88-6  [DMN65D8LDW-7_SOT363-6]  37.83 10.21 90 bottom
PR1  100K_0402_5%  [R_0402]  91.18 23.37 270 top
PR2  100K_0402_5%  [R_0402]  83.61 21.64 270 top
PR3  1M_0402_5%  [R_0402]  90.38 27.01 180 top
PR4  330K_0402_5%  [R_0402]  82.67 24.59 180 top
PR6  100K_0402_5%  [R_0402]  91.18 21.52 270 top
PR7  100K_0402_5%  [R_0402]  83.59 19.99 270 top
PR8  1M_0402_5%  [R_0402]  88.01 25.82 180 top
PR9  10K_0402_5%  [R_0402]  81.73 25.38 0 top
PR10  2.2K_0402_5%  [R_0402]  98.83 34.56 180 top
PR11  0_0402_5%  [R_0402]  97.1 31.69 90 top
PR12  33_0402_5%  [R_0402]  97.91 33.8 0 top
PR13  0_0402_5%  [R0402_0OHM]  84.55 20.81 90 top
PR14  100K_0402_1%  [R_0402]  86.76 20.41 270 bottom
PR15  0_0402_5%  [R0402_0OHM]  89.48 17.3 90 top
PR16  0_0402_5%  [R0402_0OHM]  88.67 18.19 180 top
PR17  0_0402_5%  [R0402_0OHM]  84.62 25.44 0 top
PR18  100K_0402_5%  [R_0402]  86.25 20.8 180 top
PR19  100K_0402_1%  [R_0402]  95.32 32.6 270 top
PR20  100K_0402_5%  [R_0402]  87.75 17.4 0 top
PR21  15K_0402_1%  [R_0402]  85.88 19.5 90 bottom
PR22  100K_0402_5%  [R_0402]  90.27 18.17 0 top
PR23  0_0402_5%  [R0402_0OHM]  91.18 18.93 90 top
PR24  0_0402_5%  [R_0402]  96.21 31.69 90 top
PR25  100K_0402_5%  [R_0402]  49.25 31.87 0 top
PR26  100K_0402_5%  [R_0402]  58.72 31.02 0 top
PR27  100K_0402_5%  [R_0402]  13.26 41.72 270 bottom
PR28  1M_0402_5%  [R_0402]  51.18 26.38 180 top
PR29  330K_0402_5%  [R_0402]  56.66 30.08 270 top
PR31  100K_0402_5%  [R_0402]  50.92 31.87 0 top
PR32  100K_0402_5%  [R_0402]  60.37 31.02 0 top
PR33  1M_0402_5%  [R_0402]  51.94 27.28 270 top
PR34  10K_0402_5%  [R_0402]  57.45 28.14 180 top
PR35  0_0402_5%  [R0402_0OHM]  55.62 29.92 270 top
PR36  0_0402_5%  [R0402_0OHM]  54.85 33.29 270 top
PR38  0_0402_5%  [R0402_0OHM]  55.63 24.32 0 top
PR39  100K_0402_5%  [R_0402]  55.65 31.65 270 top
PR40  100K_0402_5%  [R_0402]  53.85 32.51 90 top
PR41  0_0402_5%  [R0402_0OHM]  53.07 33.43 270 top
PR42  221K_0402_1%~D  [R_0402]  55.85 26.29 90 top
PR43  100K_0402_5%  [R_0402]  47.42 26.19 0 bottom
PR44  100K_0402_5%  [R_0402]  57.81 33.03 180 bottom
PR45  100K_0402_5%  [R_0402]  25.28 64.12 45 top
PR46  1M_0402_5%  [R_0402]  48.46 33.24 270 bottom
PR47  330K_0402_5%  [R_0402]  61.03 30.06 270 bottom
PR48  100K_0402_5%  [R_0402]  49.07 26.19 0 bottom
PR50  100K_0402_5%  [R_0402]  58.67 33.03 0 bottom
PR51  1M_0402_5%  [R_0402]  49.76 30.94 90 bottom
PR52  10K_0402_5%  [R_0402]  54.89 31.13 180 bottom
PR53  0_0402_5%  [R0402_0OHM]  53.71 33.31 0 bottom
PR54  0_0402_5%  [R0402_0OHM]  52.47 25.58 90 bottom
PR55  0_0402_5%  [R0402_0OHM]  53.52 28.68 90 bottom
PR57  100K_0402_5%  [R_0402]  53.54 26.98 90 bottom
PR58  221K_0402_1%~D  [R_0402]  55.32 29.28 90 bottom
PR59  100K_0402_5%  [R_0402]  51.66 26.49 270 bottom
PR60  0_0402_5%  [R0402_0OHM]  50.87 25.58 90 bottom
PR61  1K_0402_5%  [R_0402]  300 30.63 0 bottom
PR62  100K_0402_5%  [R_0402]  65.61 19.9 270 top
PR64  10M_0402_5%  [R_0402]  300.86 31.84 90 bottom
PR65  100_0402_5%  [R_0402]  67.57 14.72 180 top
PR66  100_0402_5%  [R_0402]  67.57 13.93 180 top
PR67  100_0402_5%  [R_0402]  67.59 15.5 180 top
PR70  100K_0402_5%  [R_0402]  79.14 16.72 90 top
PR71  100K_0402_5%  [R_0402]  66.52 29.53 180 top
PR72  100K_0402_5%  [R_0402]  65.89 29.45 180 bottom
PR74  100K_0402_5%  [R_0402]  86.33 25.81 270 top
PR75  100K_0402_5%  [R_0402]  57.31 24.32 0 top
PR76  100K_0402_5%  [R_0402]  54.62 32.53 180 bottom
PR100  4.7_1206_5%  [R_1206]  140.37 109.34 270 top
PR101  0_0603_5%  [R0603_0OHM]  138.9 112.05 0 top
PR102  0_0402_5%  [R0402_0OHM]  134.08 115.57 180 top
PR103  0_0402_5%  [R_0402]  56.1 5.61 0 bottom
PR104  0_0402_5%  [R0402_0OHM]  132.93 109.11 270 top
PR105  0_0402_5%  [R0402_0OHM]  129.08 111.88 180 top
PR106  1K_0402_5%  [R_0402]  131.71 111.96 0 top
PR107  100K_0402_5%  [R_0402]  133.16 116.35 0 top
PR108  499K_0402_1%  [R_0402]  132.67 113.69 180 top
PR109  499K_0402_1%  [R_0402]  132.67 114.45 180 top
PR110  100K_0402_5%  [R_0402]  57.02 6.38 180 bottom
PR111  0_0603_5%  [R0603_0OHM]  51.98 10.63 90 bottom
PR112  4.7_1206_5%  [R_1206]  50.85 12.4 180 top
PR113  0_0402_5%  [R0402_0OHM]  55.32 3.61 90 bottom
PR114  1K_0402_5%  [R_0402]  51.94 3.63 90 bottom
PR115  1M_0402_1%  [R_0402]  54.55 4.52 270 bottom
PR200  2.2_0603_5%  [R_0603]  118.27 12.72 180 top
PR201  6.19K_0402_1%  [R_0402]  115.62 9.04 90 top
PR202  4.7_1206_5%  [R_1206]  132.29 4.11 90 top
PR203  5.1_0603_5%  [R_0603]  110.61 8.4 90 top
PR204  2.2_0603_5%  [R_0603]  113.13 8.45 0 top
PR205  100K_0402_1%  [R_0402]  109.14 11.03 0 top
PR206  13K_0402_1%  [R_0402]  110.07 16.04 0 top
PR207  475K_0402_1%  [R_0402]  109.14 11.79 0 top
PR208  200K_0402_5%  [R_0402]  109.12 13.47 0 top
PR209  20K_0402_1%  [R_0402]  110.03 15.02 180 top
PR210  100K_0402_5%  [R_0402]  109.12 14.23 0 top
PR300  100K_0402_1%  [R_0402]  309.28 54.73 270 bottom
PR301  4.7_1206_5%  [R_1206]  305.45 61.86 180 top
PR302  2.2_0603_5%  [R_0603]  308.06 55.49 270 top
PR303  100_0402_1%  [R_0402]  305.52 64.53 0 top
PR304  0_0402_5%  [R0402_0OHM]  310.68 62.41 270 top
PR306  0_0402_5%  [R0402_0OHM]  307.2 64.54 0 top
PR307  1M_0402_1%  [R_0402]  309.74 61.5 90 top
PR308  0_0402_5%  [R_0402]  307.26 61.46 90 top
PR309  0_0402_5%  [R0402_0OHM]  308.06 62.37 270 top
PR310  0_0402_5%  [R0402_0OHM]  307.21 63.76 0 top
PR311  10K_0402_1%  [R_0402]  313.2 61.51 90 top
PR312  10K_0402_1%  [R_0402]  313.99 62.43 270 top
PR313  10K_0402_1%  [R_0402]  312.4 62.42 270 top
PR314  10K_0402_1%  [R_0402]  311.47 61.5 90 top
PR400  100K_0402_5%  [R_0402]  153.69 93.83 0 top
PR401  0_0402_5%  [R0402_0OHM]  159.46 94.92 90 top
PR402  1M_0402_5%  [R_0402]  158.67 94.92 90 top
PR403  4.7_0603_5%  [R_0603]  159.32 89.65 0 top
PR404  36.5K_0402_1%  [R_0402]  156 95.91 270 top
PR405  11.5K_0402_1%  [R_0402]  155.24 95 90 top
PR500  100K_0402_5%  [R_0402]  350.49 39.88 0 top
PR501  0_0603_5%  [R0603_0OHM]  355.6 45.24 90 top
PR502  4.7_1206_5%  [R_1206]  359.42 47.89 0 top
PR505  0_0402_5%  [R0402_0OHM]  351.64 38.09 90 top
PR506  1K_0402_5%  [R_0402]  354.99 38.09 90 top
PR507  1M_0402_1%  [R_0402]  352.4 39 270 top
PR508  0_0402_5%  [R_0402]  319.81 3.74 180 top
PR509  0_0402_5%  [R_0402]  351.41 40.67 180 top
PR510  499K_0402_1%  [R_0402]  320.9 3.23 270 top
PR511  4.7_1206_5%  [R_1206]  327.16 11.19 0 top
PR512  499K_0402_1%  [R_0402]  321.66 3.23 270 top
PR513  1K_0402_5%  [R_0402]  323.48 2.28 90 top
PR514  0_0603_5%  [R0603_0OHM]  323.29 9.35 90 top
PR515  100K_0402_5%  [R_0402]  318.89 4.51 0 top
PR700  0.005_1206_1%  [R_1206_4P-D]  90.7 32.07 0 bottom
PR701  4.02K_0402_1%  [R_0402]  69.7 17.79 270 top
PR702  100_0402_1%  [R_0402]  91.45 31.57 90 top
PR703  0_0402_5%  [R0402_0OHM]  90.66 32.46 180 top
PR704  0_0402_5%  [R0402_0OHM]  90.66 31.61 180 top
PR705  10_1206_5%  [R_1206]  79.51 25.03 180 top
PR706  274K_0402_1%  [R_0402]  69.34 27.89 90 top
PR707  4.12K_0603_1%  [R_0603]  73.06 28.77 270 top
PR708  2.2_0603_5%  [R_0603]  74.32 22.98 0 top
PR709  49.9K_0402_1%  [R_0402]  70.2 27.13 180 top
PR710  0_0402_5%  [R0402_0OHM]  65.55 23.07 0 top
PR711  0_0402_5%  [R0402_0OHM]  65.55 22.31 0 top
PR712  100K_0402_1%  [R_0402]  71.05 28.88 0 top
PR713  0_0402_5%  [R0402_0OHM]  72.02 27.23 180 top
PR714  0_0402_5%  [R0402_0OHM]  65.55 24.59 0 top
PR715  0.01_1206_1%  [R_1206_4P-D]  79.45 5.92 180 top
PR716  121K_0402_1%  [R_0402]  71.97 28.09 180 top
PR717  0_0402_5%  [R0402_0OHM]  68.55 28.83 270 top
PR718  0_0402_5%  [R0402_0OHM]  65.55 23.83 0 top
PR719  0_0402_5%  [R0402_0OHM]  65.55 25.35 0 top
PR720  20K_0402_1%  [R_0402]  75.56 19.18 180 top
PR721  3.92K_0402_1%  [R_0402]  76.27 19.18 0 top
PR722  4.7_1206_5%  [R_1206]  93.16 2.39 0 top
PR723  24.9K_0402_1%  [R_0402]  64.07 24.39 90 top
PR724  0_0402_5%  [R0402_0OHM]  66.42 19.45 0 top
PR725  10K_0402_5%  [R_0402]  68.17 19.48 270 top
PR726  2.74K_0402_1%  [R_0402]  74.17 18.42 270 top
PR727  10_0402_1%  [R_0402]  71.85 18.62 90 top
PR728  10_0402_1%  [R_0402]  71.09 18.62 90 top
PR729  0_0402_5%  [R_0402]  66.47 21.54 180 top
PR730  100K_0402_1%  [R_0402]  66.47 20.78 180 top
PR731  1M_0402_5%  [R_0402]  91.64 34.4 180 top
PR732  1M_0402_5%  [R_0402]  90.01 34.4 180 top
PR733  100K_0402_5%  [R_0402]  93.28 38.78 270 top
PR734  100K_0402_5%  [R_0402]  93.28 37.16 270 top
PR735  10_0402_1%  [R_0402]  68.88 17.79 270 top
PR800  100K_0402_5%  [R_0402]  104.31 28.01 90 top
PR801  118K_0402_1%  [R_0402]  105.46 25.97 90 top
PR802  2.2_0603_5%  [R_0603]  104.98 33.13 90 top
PR803  499_0402_1%  [R_0402]  107.24 25.97 90 top
PR804  470K_0402_1%  [R_0402]  109.9 27.75 90 top
PR805  4.7_1206_5%  [R_1206]  109.92 42.41 270 top
PR807  4.99K_0402_1%  [R_0402]  109.4 27.02 270 top
PR808  10K_0402_1%  [R_0402]  108.63 27.02 270 top
PR809  10_0402_1%  [R_0402]  110.28 27.02 270 top
PR810  0_0402_5%  [R0402_0OHM]  139.77 20.7 90 top
PR811  0_0402_5%  [R0402_0OHM]  140.73 20.7 90 top
PR812  0_0402_5%  [R_0402]  102.37 27.98 0 top
PR900  100K_0402_5%  [R_0402]  96.7 19.79 0 top
PR901  0_0402_5%  [R0402_0OHM]  102.05 21.71 90 top
PR902  1M_0402_5%  [R_0402]  101.26 21.71 90 top
PR903  4.7_0603_5%  [R_0603]  103.4 22.52 0 top
PR904  200K_0402_1%  [R_0402]  98.62 22.62 270 top
PR905  100K_0402_1%  [R_0402]  97.86 21.71 90 top
PR906  0_0402_5%  [R0402_0OHM]  102.37 27.18 0 top
PR1100  100_0402_1%  [R_0402]  261.39 59.68 180 top
PR1101  12K_0402_1%  [R_0402]  311.14 42.98 180 top
PR1102  7.5K_0603_1%  [R_0603]  279.04 64.29 90 bottom
PR1103  499_0402_1%  [R_0402]  311.41 37.21 180 top
PR1104  45.3_0402_1%  [R_0402]  311.41 40.07 180 top
PR1105  100_0402_1%  [R_0402]  310.5 38.17 0 top
PR1106  0_0402_5%  [R0402_0OHM]  308.18 51.8 0 top
PR1107  1K_0402_5%  [R_0402]  310.38 49.48 270 top
PR1108  0_0402_5%  [R0402_0OHM]  308.18 50.91 0 top
PR1109  1.65K_0402_1%  [R_0402]  309.5 49.48 270 top
PR1110  100_0402_1%  [R_0402]  308.34 37.21 0 top
PR1111  100_0402_1%  [R_0402]  261.39 60.47 180 top
PR1112  29.4K_0402_1%  [R_0402]  305.95 43.29 0 bottom
PR1113  10_0402_1%  [R_0402]  307.69 38.5 0 top
PR1114  10K_0402_1%  [R_0402]  309.27 42.05 180 top
PR1115  0_0402_5%  [R0402_0OHM]  307.73 39.42 0 top
PR1116  12.4K_0402_1%  [R_0402]  309.32 44.71 180 top
PR1117  49.9_0402_1%  [R_0402]  308.35 40.2 0 top
PR1118  1.5K_0402_1%  [R_0402]  310.71 47.37 180 top
PR1119  100_0402_1%  [R_0402]  262.28 49.16 180 top
PR1120  37.4K_0402_1%  [R_0402]  306.75 41.53 180 bottom
PR1121  0_0402_5%  [R0402_0OHM]  305.93 48.68 0 bottom
PR1122  0_0402_5%  [R0402_0OHM]  304.88 50.51 90 bottom
PR1123  1.21K_0402_1%  [R_0402]  305.68 51.4 0 bottom
PR1124  100_0402_1%  [R_0402]  261.13 41.41 0 top
PR1125  100_0402_1%  [R_0402]  262.28 49.93 180 top
PR1126  0_0402_5%  [R0402_0OHM]  307.78 35.08 270 top
PR1127  1.05K_0402_1%  [R_0402]  306.89 36.78 270 top
PR1128  0_0402_5%  [R0402_0OHM]  305.99 34.17 0 top
PR1129  100_0402_1%  [R_0402]  261.13 40.62 0 top
PR1130  49.9_0402_1%  [R_0402]  305.91 48.63 90 top
PR1131  1K_0402_1%  [R_0402]  305.93 47.75 0 top
PR1132  27.4K_0402_1%  [R_0402]  303.27 45.39 90 bottom
PR1133  3.65K_0402_1%  [R_0402]  304.14 47.72 90 top
PR1134  49.9_0402_1%  [R_0402]  305.11 36.03 270 top
PR1135  27.4K_0402_1%  [R_0402]  304.8 39.51 0 bottom
PR1136  1K_0402_1%  [R_0402]  304.21 36.79 0 top
PR1137  3.65K_0402_1%  [R_0402]  304.16 33.35 180 top
PR1138  30.1K_0402_1%  [R_0402]  303.27 48.66 270 top
PR1139  11K_0402_1%  [R_0402]  302.54 35.99 180 top
PR1140  75K_0402_1%  [R_0402]  303.28 50.42 180 top
PR1141  75K_0402_1%  [R_0402]  301.58 35.16 0 top
PR1142  174K_0402_1%  [R_0402]  302.4 49.53 180 top
PR1143  88.7K_0603_1%  [R_0603]  300.86 52.45 270 top
PR1144  174K_0402_1%  [R_0402]  302.52 33.16 180 top
PR1145  61.9K_0603_1%  [R_0603]  298.58 36.24 180 top
PR1146  88.7K_0603_1%  [R_0603]  299.54 52.43 270 top
PR1148  88.7K_0603_1%  [R_0603]  298.24 52.4 270 top
PR1149  88.7K_0603_1%  [R_0603]  296.95 52.4 270 top
PR1150  1K_0402_1%  [R_0402]  296.16 46.5 0 top
PR1151  2.2_0603_5%  [R_0603]  295.92 45.35 0 top
PR1152  25.5K_0402_1%  [R_0402]  299.08 41.42 0 bottom
PR1153  24.9K_0402_1%  [R_0402]  299.21 40.02 0 bottom
PR1154  2.26K_0402_1%  [R_0402]  300.86 52.19 270 bottom
PR1155  100K_0402_1%  [R_0402]  299.08 44.72 0 bottom
PR1156  4.3K_0402_1%  [R_0402]  299.46 43.07 0 bottom
PR1157  24.9K_0402_1%  [R_0402]  297.84 42.81 180 top
PR1158  97.6K_0402_1%  [R_0402]  299.08 42.31 0 bottom
PR1160  2.26K_0402_1%  [R_0402]  297.97 37.23 180 top
PR1161  2.26K_0402_1%  [R_0402]  299.54 52.26 270 bottom
PR1163  2.26K_0402_1%  [R_0402]  298.3 52.26 270 bottom
PR1164  2.26K_0402_1%  [R_0402]  296.95 52.24 270 bottom
PR1165  0_0402_5%  [R0402_0OHM]  297.08 47.51 180 bottom
PR1166  0_0402_5%  [R0402_0OHM]  297.84 41.29 180 top
PR1167  61.9K_0402_1%  [R_0402]  295.15 47.44 270 bottom
PR1168  61.9K_0402_1%  [R_0402]  295.81 41.29 180 top
PR1169  10_0402_1%  [R_0402]  311.12 43.94 180 top
PR1170  1K_0402_1%  [R_0402]  297.05 38.11 0 top
PR1171  97.6K_0402_1%  [R_0402]  297.84 42.05 180 top
PR1198  0_0402_5%  [R0402_0OHM]  308.35 41.13 0 top
PR1199  45.3_0402_1%  [R_0402]  311.4 39.12 180 top
PR1200  2_0603_5%  [R_0603]  291.92 55.8 90 top
PR1201  3.9_0603_1%  [R_0603]  291.81 58.35 0 top
PR1202  2.2_1206_1%  [R_1206]  283.41 56.09 90 bottom
PR1203  10_0402_1%  [R_0402]  277.75 53.18 0 top
PR1204  3.9_0603_1%  [R_0603]  292.02 47.34 0 top
PR1205  2_0603_5%  [R_0603]  292.11 44.74 90 top
PR1206  2.2_1206_1%  [R_1206]  284.68 45.29 90 bottom
PR1207  10_0402_1%  [R_0402]  278.35 51.43 0 top
PR1208  2_0603_5%  [R_0603]  291.99 35.03 90 top
PR1209  3.9_0603_1%  [R_0603]  291.89 37.62 0 top
PR1210  2.2_1206_1%  [R_1206]  284.68 36.4 90 bottom
PR1211  3.9_0603_1%  [R_0603]  291.79 26.37 0 top
PR1212  2_0603_5%  [R_0603]  291.92 23.88 90 top
PR1213  2.2_1206_1%  [R_1206]  284.17 25.86 90 bottom
PR1214  10_0402_1%  [R_0402]  278.11 33.37 0 top
PR1215  10_0402_1%  [R_0402]  278.15 31.21 0 top
PR1216  0_0402_5%  [R_0402]  289.91 52.45 90 bottom
PR1217  0_0402_5%  [R_0402]  288.17 52.45 90 bottom
PR1218  0_0402_5%  [R_0402]  289.76 44.48 270 bottom
PR1219  0_0402_5%  [R_0402]  289 44.48 270 bottom
PR1220  0_0402_5%  [R_0402]  288.77 34.75 270 bottom
PR1221  0_0402_5%  [R_0402]  288 34.75 270 bottom
PR1222  0_0402_5%  [R_0402]  289.51 23.7 270 bottom
PR1223  0_0402_5%  [R_0402]  288.74 23.7 270 bottom
PR1700  2_0603_5%  [R_0603]  292.05 13.92 90 top
PR1701  3.9_0603_1%  [R_0603]  291.98 16.4 0 top
PR1702  2.2_1206_1%  [R_1206]  284.46 15.91 90 bottom
PR1703  10_0402_1%  [R_0402]  278.28 16.42 270 bottom
PR1800  3.9_0603_1%  [R_0603]  289.78 68.23 0 top
PR1801  2_0603_5%  [R_0603]  289.86 65.67 90 top
PR1802  2.2_1206_1%  [R_1206]  281.51 65.23 90 bottom
PR2003  100K_0402_5%  [R_0402]  62.58 15.14 0 top
PR2005  100K_0402_5%  [R_0402]  59.38 19.05 90 top
PR2007  100K_0402_5%  [R_0402]  60.7 15.52 90 top
PR2008  100K_0402_5%  [R_0402]  60.7 18.09 270 top
PR2009  0_0402_5%  [R0402_0OHM]  73.61 27.41 270 bottom
PR2010  100K_0402_5%  [R_0402]  57.17 21.26 90 top
PR2014  0_0402_5%  [R_0402]  58.93 14.87 0 top
PR2016  100K_0402_5%  [R_0402]  56.21 23.02 0 top
PR2018  100K_0402_5%  [R_0402]  56.84 17.55 90 top
PR2019  0_0402_5%  [R0402_0OHM]  53.36 25.05 0 bottom
PR2020  0_0402_5%  [R0402_0OHM]  52.73 13.1 180 bottom
PR2021  100K_0402_5%  [R_0402]  55.93 19.31 0 top
PR2022  287K_0402_1%  [R_0402]  53.41 24.26 270 bottom
PR2023  137K_0402_1%  [R_0402]  50.9 24.31 270 bottom
PR2024  221K_0402_1%~D  [R_0402]  50.24 19.4 270 bottom
PR2025  221K_0402_1%~D  [R_0402]  51.98 22.8 180 top
PR2026  287K_0402_1%  [R_0402]  53.72 14.51 90 bottom
PR2027  137K_0402_1%  [R_0402]  51.23 14.48 90 bottom
PR2028  221K_0402_1%~D  [R_0402]  50.44 15.12 270 bottom
PR2029  221K_0402_1%~D  [R_0402]  52.96 18.19 180 top
PR2030  1M_0402_1%  [R_0402]  54.58 21.34 270 bottom
PR2031  1M_0402_1%  [R_0402]  54.61 17.66 90 bottom
PR2032  23.7K_0402_1%  [R_0402]  54.2 23.35 90 bottom
PR2033  84.5K_0402_1%  [R_0402]  51.69 23.4 90 bottom
PR2034  23.7K_0402_1%  [R_0402]  54.5 15.42 270 bottom
PR2035  84.5K_0402_1%  [R_0402]  52.01 15.39 270 bottom
PR2036  0_0402_5%  [R0402_0OHM]  79.65 23.26 180 bottom
PR2037  10K_0402_1%  [R_0402]  72.87 25.67 180 bottom
PR2038  221K_0402_1%~D  [R_0402]  69.81 27.57 180 bottom
PR2039  10K_0402_1%  [R_0402]  75.76 27.47 90 bottom
PR2040  287K_0402_1%  [R_0402]  77.92 23.18 90 bottom
PR2041  137K_0402_1%  [R_0402]  74.67 26.61 0 bottom
PR2042  1.8M_0402_1%  [R_0402]  78.74 24.02 0 bottom
PR2047  287K_0402_1%  [R_0402]  35.45 18.8 0 bottom
PR2048  137K_0402_1%  [R_0402]  33.25 14.81 90 bottom
PR2050  137K_0402_1%  [R_0402]  47.42 15.5 90 bottom
PR2051  287K_0402_1%  [R_0402]  46.43 17.81 90 bottom
PR2053  23.7K_0402_1%  [R_0402]  77.16 24.09 270 bottom
PR2054  1.8M +-1% 0402  [R_0402]  34.82 17.49 270 bottom
PR2055  1.8M +-1% 0402  [R_0402]  45.66 18.72 270 bottom
PR2056  84.5K_0402_1%  [R_0402]  75.59 25.8 180 bottom
PR2059  82.5K_0402_1%  [R_0402]  36.37 19.56 180 bottom
PR2060  82.5K_0402_1%  [R_0402]  44.85 18.8 180 bottom
PR2061  84.5K_0402_1%  [R_0402]  34.03 15.73 270 bottom
PR2062  84.5K_0402_1%  [R_0402]  47.34 17.86 90 bottom
PR2063  221K_0402_1%~D  [R_0402]  39.93 20.88 90 bottom
PR2064  221K_0402_1%~D  [R_0402]  43.8 20.77 90 bottom
PR2065  0_0402_5%  [R0402_0OHM]  38.48 23 0 bottom
PR2066  0_0402_5%  [R0402_0OHM]  42.52 22.61 0 bottom
PR2100  300K_0402_1%  [R_0402]  38.43 28.39 90 bottom
PR2101  1M_0402_1%  [R_0402]  37.96 33.79 90 top
PR2104  300K_0402_1%  [R_0402]  40.51 29.99 0 bottom
PR2105  1M_0402_1%  [R_0402]  41.45 34.28 180 top
PR2106  0_0402_5%  [R0402_0OHM]  39.72 25.64 90 bottom
PR2108  100K_0402_1%  [R_0402]  37.72 35.69 0 bottom
PR2109  100K_0402_1%  [R_0402]  41.4 35.57 0 bottom
PR2134  100K_0402_1%  [R_0402]  37.67 29.3 270 bottom
PR2142  100K_0402_1%  [R_0402]  42.29 29.99 0 bottom
PR2143  1M_0402_5%  [R_0402]  95.21 25.57 0 bottom
PR2144  200K_0402_1%  [R_0402]  82.83 23.64 180 bottom
PR2145  100K_0402_1%  [R_0402]  84.11 26.27 180 bottom
PR2146  100K_0402_1%  [R_0402]  83.18 27.07 0 bottom
PR2147  200K_0402_1%  [R_0402]  83.18 29.73 270 bottom
PR2148  1M_0402_1%  [R_0402]  84.4 23.08 270 bottom
PR2149  221K_0402_1%  [R_0402]  78.23 28.84 0 bottom
PR2150  0_0402_5%  [R0402_0OHM]  33.96 26.38 0 bottom
PR2151  100K_0402_5%  [R_0402]  59.38 21.64 270 top
PR2152  0_0402_5%  [R0402_0OHM]  36.55 13.1 270 bottom
PR2153  0_0402_5%  [R0402_0OHM]  32.84 13.36 270 bottom
PR2154  0_0402_5%  [R0402_0OHM]  36.9 9.91 90 bottom
PR2155  0_0402_5%  [R0402_0OHM]  44.75 12.93 270 bottom
PR2156  0_0402_5%  [R0402_0OHM]  40.64 12.61 270 bottom
PR2157  0_0402_5%  [R0402_0OHM]  40.71 10.01 90 bottom
PR2158  49.9K_0402_1%  [R_0402]  40.27 13.97 180 bottom
PR2159  49.9K_0402_1%  [R_0402]  42.21 14.15 0 bottom
PR2161  0_0402_5%  [R0402_0OHM]  97.59 27.86 180 top
PR2162  0_0402_5%  [R0402_0OHM]  97.58 25.55 0 bottom
PR2163  100K_0402_5%  [R_0402]  50.42 36.97 270 top
PU1  TC7SH08FU_SSOP5~D  [TC7SH08FU_SSOP5]  86.59 18.46 90 top
PU100  -  [SY8288BRAC_QFN20_3X3]  137.36 111.58 180 top
PU101  -  [SY8288CRAC_QFN20_3X3]  52.12 9.19 270 bottom
PU200  -  [RT8207PGQW_WQFN20_3X3]  113.97 14.75 180 top
PU300  -  [NB681GD-Z_QFN13_2X3]  310.33 57.94 180 top
PU400  -  [G5719CRC1U_TDFN8_2X2]  156.05 93.9 270 top
PU500  -  [SY8288CRAC_QFN20_3X3]  355.9 43.72 270 top
PU501  -  [SY8288BRAC_QFN20_3X3]  323.62 7.9 270 top
PU700  BQ24780SRUYR_QFN28_4X4  [BQ24780RUYR_WQFN28_4X4]  71.28 25.28 270 top
PU800  -  [TPS51212DSCR_SON10_3X3]  106.17 28.26 0 top
PU900  -  [G5719CRC1U_TDFN8_2X2]  98.99 20.18 270 top
PU1100  -  [NCP81215DMNTXG_QFN52_6X6]  305.55 45.5 270 top
